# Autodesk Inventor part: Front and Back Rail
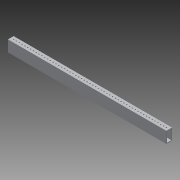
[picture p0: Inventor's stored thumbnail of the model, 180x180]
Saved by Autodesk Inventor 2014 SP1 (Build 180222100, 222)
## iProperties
Created: 2014-06
Part Number: Front and Back Rail
Material: Aluminum 6061
Document SubType Name: Modeling
Designer: Michael
Density: 2.71 g/cm^3
Appearance: Aluminum - Flat
Mass: 435.658 g
Surface Area: 2057.27 cm^2
Volume: 160.76 cm^3
Author: Michael
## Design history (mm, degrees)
sketch "Sketch1"
  geometry: L1 (-355.6, -25.4)-(355.6, -25.4); L2 (355.6, -25.4)-(355.6, 25.4); L3 (355.6, 25.4)-(-355.6, 25.4); L4 (-355.6, 25.4)-(-355.6, -25.4); L5 (-355.6, -25.4)-(355.6, 25.4); L6 (355.6, -25.4)-(-355.6, 25.4); 1 further point
  constraints: 12 end point, 2 midpoint, 2 parallel, 1 horizontal, 1 perpendicular
  dimensions: "d0" = 711.2 distance between parallel lines of L2 L4; "d1" = 50.8 distance between parallel lines of L1 L3
extrude "Extrusion1" new body sketch "Sketch1" distance "d2" = 25.4; taper "d3" = 0 deg
sketch "Sketch2"
  geometry: L1 (0, 0)-(0, 50.8) reference; L2 (0, 50.8)-(-25.4, 50.8) reference; L3 (-25.4, 0)-(-25.4, 50.8) reference; L4 (0, 0)-(-25.4, 0) reference; L5 (-3.175, 47.625)-(-3.175, 3.175); L6 (-3.175, 3.175)-(-22.225, 3.175); L7 (-22.225, 3.175)-(-22.225, 47.625); L8 (-22.225, 47.625)-(-3.175, 47.625); 1 further point
  constraints: 8 end point, 3 other
  dimensions: "d4" = 3.175 distance between parallel lines of L2 L8
extrude "Extrusion2" cut sketch "Sketch2" stored distance "d5" = 25.4; taper "d6" = 0 deg
sketch "Sketch3"
  geometry: L1 (0, 0)-(0, -25.4) reference; C1 r 2.489 at (12.7, -12.7); 2 further points
  constraints: 1 centre point, 1 horizontal alignment, 1 midpoint
  dimensions: "d7" = 4.9784 diameter of C1; "d8" = 12.7 distance from line of L1 C1.centre
extrude "Extrusion3" cut sketch "Sketch3" stored distance "d9" = 25.4; taper "d10" = 0 deg
mirror "Mirror1"
sketch "Sketch4"
  geometry: L1 (711.2, 0)-(0, 0) reference; C1 r 2.489 at (368.3, -12.7) reference; C2 r 2.489 at (355.6, -12.7); 2 further points
  constraints: 1 centre point, 1 horizontal alignment, 1 midpoint, 1 vertical alignment
  dimensions: "d14" = 4.9784 diameter of C2 (= d15); "d15" = 4.9784 diameter of C1 (derived)
extrude "Extrusion4" cut sketch "Sketch4" stored distance "d16" = 25.4; taper "d17" = 0 deg
body "Solid1"
pattern_linear "Rectangular Pattern1" dims "d13" = 12.7
